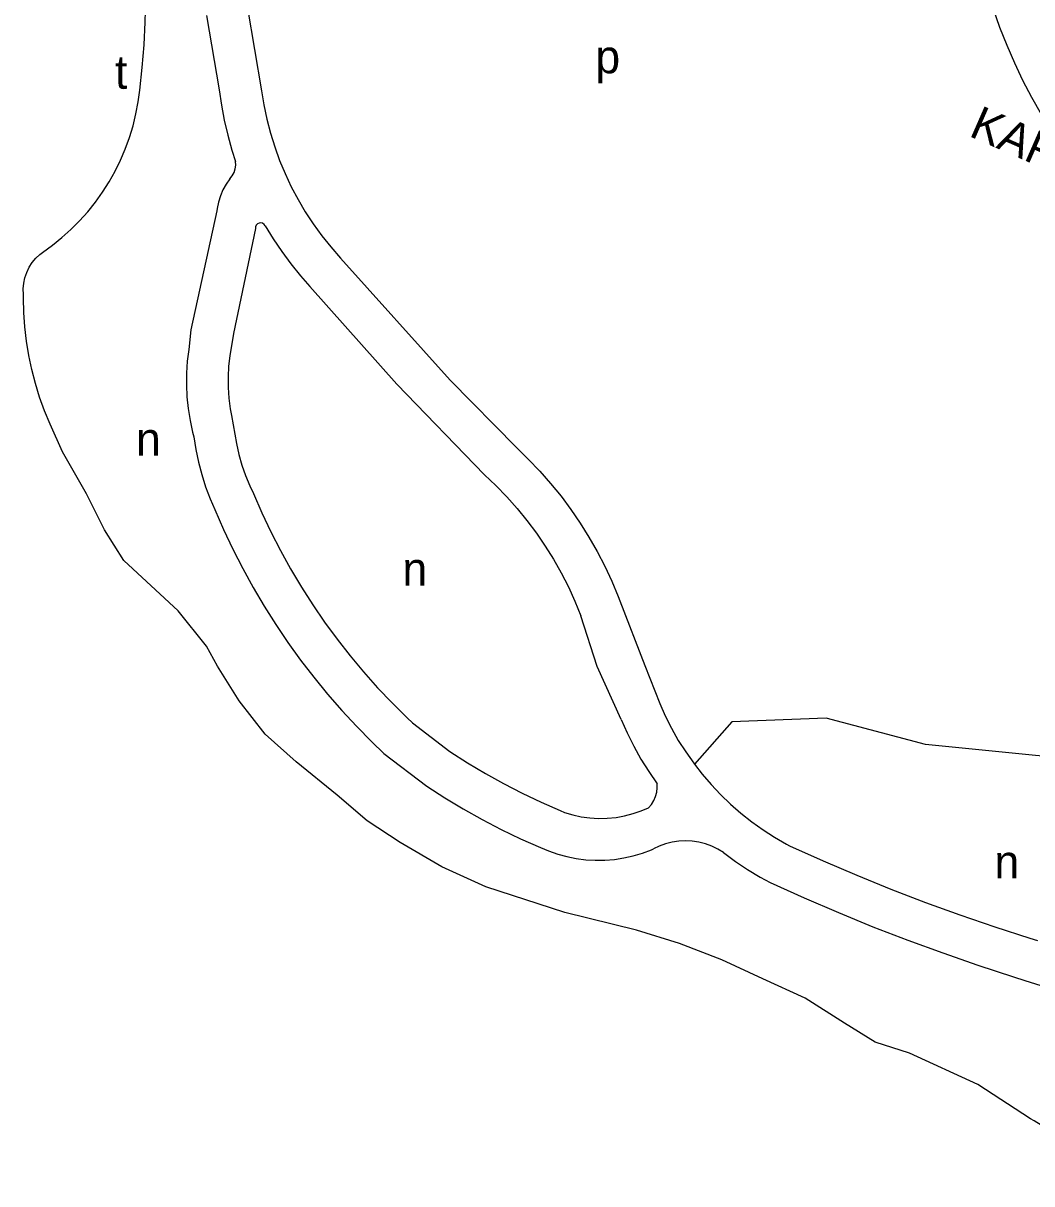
# Model space of a CAD drawing. Extents: x 161141 to 163125, y 381621 to 383200.
# Drawn here: x 161143.2 to 161264.1, y 381771.4 to 381910.5 of the extents above; entities that cross this region are included whole.
import ezdxf

# ---------------------------------------------------------------- set-up
doc = ezdxf.new("R2010")
doc.units = 0
for name, color, linetype in [('BLT_Basislijn', 7, 'Continuous'), ('BLT_Centroide', 7, 'Continuous'), ('BLT_Straatnaam_verkleind', 7, 'Continuous')]:
    doc.layers.add(name, color=color, linetype=linetype)

msp = doc.modelspace()

# ---------------------------------------------------------------- linework, layer by layer
at = {"layer": 'BLT_Basislijn'}
for p, q in [((161170.05, 381912.28), (161171.72, 381902.4)), ((161165.13, 381911.41), (161166.67, 381902.49)), ((161166.36, 381887.99), (161163.24, 381873.75)), ((161171.01, 381885.88), (161168.39, 381873.3)), ((161181.21, 381882.31), (161194.34, 381867.69)), ((161177.52, 381878.93), (161187.94, 381867.23)), ((161163.24, 381873.75), (161163, 381871.38)), ((161168.39, 381873.3), (161167.95, 381870.63)), ((161202.29, 381859.63), (161194.34, 381867.69)), ((161198.44, 381856.37), (161187.94, 381867.23)), ((161168.14, 381863.45), (161168.72, 381860.12)), ((161189.82, 381826.62), (161194.3, 381823.21)), ((161186.4, 381822.97), (161191.53, 381819.05)), ((161263.22, 381795.75), (161277.97, 381791.08))]:
    msp.add_line(p, q, dxfattribs=at)
for points in [[(161266.41, 381897.57), (161265.21, 381899.55), (161264.07, 381901.57), (161263, 381903.62), (161262.01, 381905.71), (161261.09, 381907.84), (161260.24, 381909.99), (161259.46, 381912.17), (161258.77, 381914.38), (161258.15, 381916.61), (161257.6, 381918.86), (161257.14, 381921.13), (161256.75, 381923.42), (161256.44, 381925.71), (161256.21, 381928.02), (161256.07, 381930.33), (161256, 381932.64), (161256.01, 381934.96), (161256.1, 381937.27), (161256.27, 381939.58), (161256.52, 381941.88), (161256.85, 381944.18), (161257.04, 381945.28)], [(161157.13, 381902.47), (161157.43, 381905.18), (161157.65, 381907.9), (161157.8, 381910.63), (161157.86, 381913.36), (161157.84, 381916.09), (161157.75, 381918.81), (161157.57, 381921.54), (161157.31, 381924.26), (161157.13, 381925.8)], [(161145.47, 381883.02), (161146.66, 381883.87), (161147.8, 381884.79), (161148.89, 381885.77), (161149.93, 381886.8), (161150.91, 381887.9), (161151.82, 381889.04), (161152.68, 381890.23), (161153.46, 381891.47), (161154.18, 381892.75), (161154.83, 381894.06), (161155.4, 381895.41), (161155.9, 381896.79), (161156.33, 381898.19), (161156.68, 381899.61), (161156.94, 381901.06), (161157.13, 381902.47)], [(161166.67, 381902.49), (161166.93, 381900.67), (161167.27, 381898.86), (161167.69, 381897.07), (161168.18, 381895.29), (161168.62, 381893.92)], [(161171.72, 381902.4), (161172, 381900.7), (161172.36, 381899), (161172.8, 381897.33), (161173.31, 381895.68), (161173.9, 381894.05), (161174.56, 381892.46), (161175.3, 381890.89), (161176.11, 381889.36), (161176.98, 381887.87), (161177.93, 381886.43), (161178.94, 381885.02), (161180.02, 381883.67), (161181.21, 381882.31)], [(161167.94, 381891.85), (161168.22, 381892.21), (161168.44, 381892.6), (161168.58, 381893.02), (161168.64, 381893.47), (161168.62, 381893.92)], [(161167.94, 381891.85), (161167.49, 381891.21), (161167.11, 381890.53), (161166.8, 381889.81), (161166.56, 381889.06), (161166.4, 381888.29), (161166.36, 381887.99)], [(161172.15, 381886.2), (161172.03, 381886.38), (161171.86, 381886.51), (161171.65, 381886.57), (161171.43, 381886.54), (161171.23, 381886.44), (161171.09, 381886.28), (161171.01, 381886.08), (161171.01, 381885.88)], [(161172.15, 381886.2), (161173.12, 381884.63), (161174.15, 381883.11), (161175.24, 381881.63), (161176.4, 381880.2), (161177.52, 381878.93)], [(161143.18, 381877.98), (161143.17, 381878.66), (161143.23, 381879.33), (161143.37, 381879.99), (161143.59, 381880.62), (161143.89, 381881.23), (161144.25, 381881.79), (161144.68, 381882.31), (161145.16, 381882.78), (161145.47, 381883.02)], [(161146.38, 381862.43), (161145.72, 381864.03), (161145.13, 381865.65), (161144.62, 381867.3), (161144.18, 381868.98), (161143.82, 381870.67), (161143.54, 381872.38), (161143.34, 381874.1), (161143.22, 381875.82), (161143.18, 381877.55), (161143.18, 381877.98)], [(161163, 381871.38), (161162.83, 381869.97), (161162.73, 381868.55), (161162.72, 381867.13), (161162.79, 381865.7), (161162.93, 381864.29), (161163.16, 381862.88), (161163.46, 381861.49), (161163.61, 381860.93)], [(161167.95, 381870.63), (161167.79, 381869.37), (161167.72, 381868.09), (161167.73, 381866.82), (161167.82, 381865.55), (161167.99, 381864.28), (161168.14, 381863.45)], [(161152.9, 381849.75), (161150.75, 381854.09), (161147.86, 381859.13), (161146.38, 381862.43)], [(161163.61, 381860.93), (161163.85, 381859.4), (161164.17, 381857.89), (161164.56, 381856.39), (161165.03, 381854.92), (161165.58, 381853.47), (161166.14, 381852.2)], [(161168.72, 381860.12), (161169.01, 381858.81), (161169.37, 381857.53), (161169.81, 381856.26), (161170.32, 381855.03), (161170.75, 381854.12)], [(161202.29, 381859.63), (161203.71, 381858.25), (161205.08, 381856.81), (161206.38, 381855.32), (161207.63, 381853.78), (161208.81, 381852.19), (161209.93, 381850.55), (161210.98, 381848.87), (161211.96, 381847.15), (161212.88, 381845.39), (161213.71, 381843.6), (161214.48, 381841.77), (161214.69, 381841.24)], [(161198.44, 381856.37), (161199.81, 381855.08), (161201.12, 381853.73), (161202.37, 381852.33), (161203.55, 381850.88), (161204.68, 381849.37), (161205.74, 381847.82), (161206.74, 381846.23), (161207.66, 381844.6), (161208.52, 381842.92), (161209.3, 381841.22), (161210.02, 381839.46)], [(161170.75, 381854.12), (161171.76, 381851.81), (161172.84, 381849.53), (161173.99, 381847.28), (161175.21, 381845.07), (161176.51, 381842.9), (161177.87, 381840.77), (161179.29, 381838.69), (161180.79, 381836.66), (161182.34, 381834.67), (161183.96, 381832.73), (161185.64, 381830.84), (161187.38, 381829.01), (161189.17, 381827.23), (161189.82, 381826.62)], [(161166.14, 381852.2), (161167.18, 381849.81), (161168.29, 381847.46), (161169.47, 381845.14), (161170.72, 381842.86), (161172.04, 381840.62), (161173.43, 381838.42), (161174.89, 381836.26), (161176.41, 381834.15), (161178, 381832.09), (161179.65, 381830.08), (161181.36, 381828.11), (161183.13, 381826.21), (161184.96, 381824.35), (161186.4, 381822.97)], [(161249.4, 381787.02), (161245.27, 381788.34), (161241.6, 381790.64), (161236.88, 381793.61), (161231.81, 381795.95), (161226.89, 381798.23), (161221.83, 381800.17), (161216.67, 381801.78), (161208.1, 381803.89), (161198.61, 381806.97), (161193.35, 381809.37), (161188.36, 381812.27), (161184.39, 381814.87), (161180.8, 381817.96), (161175.87, 381821.95), (161172.15, 381825.28), (161169.06, 381829.28), (161166.46, 381833.42), (161165.12, 381835.82), (161161.74, 381840.07), (161155.21, 381846.1), (161152.9, 381849.75)], [(161214.69, 381841.24), (161217.67, 381833.49), (161219.46, 381828.96)], [(161214.85, 381827.03), (161211.95, 381833.37), (161210.02, 381839.46)], [(161219.46, 381828.96), (161220.13, 381827.45), (161220.88, 381825.97), (161221.69, 381824.53), (161222.58, 381823.14), (161223.53, 381821.78), (161223.62, 381821.66)], [(161286.9, 381810.74), (161283.06, 381818.9), (161279.6, 381821.28), (161264.11, 381822.76), (161251.32, 381824.05), (161239.41, 381827.19), (161228.11, 381826.76), (161223.62, 381821.66)], [(161214.85, 381827.03), (161215.56, 381825.42), (161216.35, 381823.83), (161217.21, 381822.29), (161218.14, 381820.78), (161219.14, 381819.32)], [(161194.3, 381823.21), (161196.41, 381821.85), (161198.56, 381820.56), (161200.75, 381819.34), (161202.98, 381818.19), (161205.24, 381817.11), (161207.53, 381816.11), (161208.04, 381815.89)], [(161223.62, 381821.66), (161224.54, 381820.48), (161225.62, 381819.23), (161226.75, 381818.03), (161227.95, 381816.88), (161229.19, 381815.8), (161230.49, 381814.77), (161231.84, 381813.81), (161233.23, 381812.92), (161234.66, 381812.09), (161235.02, 381811.9)], [(161191.53, 381819.05), (161193.7, 381817.65), (161195.91, 381816.32), (161198.17, 381815.05), (161200.46, 381813.86), (161202.79, 381812.73), (161205.15, 381811.68), (161206.14, 381811.27)], [(161218.13, 381816.44), (161218.47, 381816.85), (161218.75, 381817.31), (161218.96, 381817.8), (161219.1, 381818.32), (161219.15, 381818.85), (161219.14, 381819.32)], [(161208.04, 381815.89), (161209.04, 381815.6), (161210.06, 381815.38), (161211.1, 381815.24), (161212.14, 381815.18), (161213.18, 381815.2), (161214.22, 381815.3), (161215.25, 381815.48), (161216.26, 381815.74), (161217.25, 381816.07), (161218.13, 381816.44)], [(161227.1, 381811.07), (161226.41, 381811.49), (161225.69, 381811.84), (161224.93, 381812.12), (161224.15, 381812.32), (161223.36, 381812.44), (161222.55, 381812.48), (161221.75, 381812.45), (161220.95, 381812.33), (161220.17, 381812.13), (161219.41, 381811.86), (161218.7, 381811.52)], [(161235.02, 381811.9), (161239.04, 381810.1), (161243.1, 381808.36), (161247.18, 381806.7), (161251.3, 381805.11), (161255.44, 381803.6), (161259.61, 381802.17), (161263.81, 381800.81), (161264.73, 381800.52)], [(161206.14, 381811.27), (161207.23, 381810.89), (161208.33, 381810.59), (161209.46, 381810.36), (161210.6, 381810.22), (161211.74, 381810.15), (161212.89, 381810.17), (161214.03, 381810.26), (161215.17, 381810.43), (161216.29, 381810.69), (161217.39, 381811.02), (161218.46, 381811.42), (161218.7, 381811.52)], [(161227.1, 381811.07), (161228.53, 381810.02), (161230, 381809.04), (161231.51, 381808.12), (161232.68, 381807.48)], [(161232.68, 381807.48), (161236.76, 381805.65), (161240.87, 381803.88), (161245.01, 381802.19), (161249.18, 381800.58), (161253.38, 381799.04), (161257.61, 381797.57), (161261.86, 381796.18), (161263.22, 381795.75)], [(161263.92, 381779.15), (161257.61, 381783.29), (161249.4, 381787.02)], [(161270.1, 381771.37), (161269.83, 381772.31), (161269.49, 381773.22), (161269.07, 381774.1), (161268.58, 381774.94), (161268.02, 381775.74), (161267.4, 381776.49), (161266.72, 381777.19), (161265.98, 381777.83), (161265.2, 381778.4), (161264.36, 381778.91), (161263.92, 381779.15)]]:
    msp.add_lwpolyline(points, dxfattribs=at)

# ---------------------------------------------------------------- texts
at = {"layer": 'BLT_Centroide'}
for s, p in [('t', (161154.17, 381902.63)), ('p', (161211.74, 381904.49)), ('n', (161156.68, 381858.64)), ('n', (161188.62, 381843.07)), ('n', (161259.58, 381807.97))]:
    msp.add_text(s, height=4, dxfattribs=at).set_placement(p)
at = {"layer": 'BLT_Straatnaam_verkleind'}
msp.add_text('KAREL VAN DEN WOESTIJNELAAN', height=4, rotation=336.3499, dxfattribs=at).set_placement((161256.39, 381897.02))

doc.saveas('drawing.dxf')
